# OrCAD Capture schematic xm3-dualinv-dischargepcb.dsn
size A; title: XM3 Discharge PCB; rev: V1; company: Wolfspeed; note: 535 W Research Center Blvd.; note: Fayetteville, AR, 72701
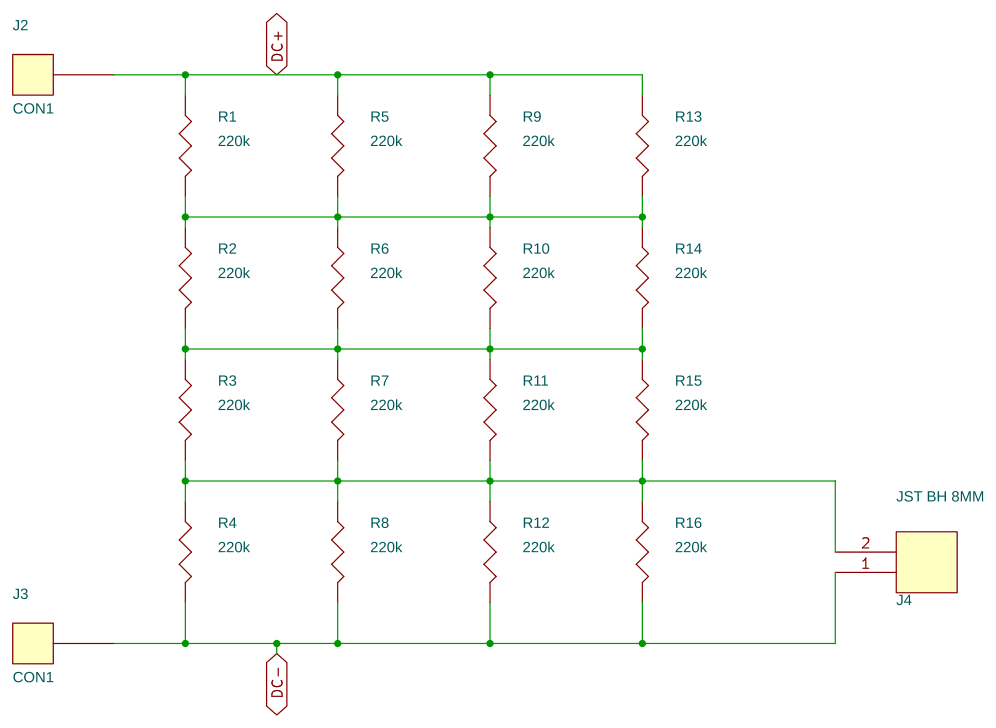
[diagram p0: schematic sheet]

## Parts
J2  CON1  [CON_1x1]
J3  CON1  [CON_1x1]
J4  JST BH 8MM  [CON_JST-BHS-8MM-2PIN]
R1  220k  [RESC6432X70N]
R2  220k  [RESC6432X70N]
R3  220k  [RESC6432X70N]
R4  220k  [RESC6432X70N]
R5  220k  [RESC6432X70N]
R6  220k  [RESC6432X70N]
R7  220k  [RESC6432X70N]
R8  220k  [RESC6432X70N]
R9  220k  [RESC6432X70N]
R10  220k  [RESC6432X70N]
R11  220k  [RESC6432X70N]
R12  220k  [RESC6432X70N]
R13  220k  [RESC6432X70N]
R14  220k  [RESC6432X70N]
R15  220k  [RESC6432X70N]
R16  220k  [RESC6432X70N]

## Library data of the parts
J2 J3 = CON1
J4 = CON2: CONN HEADER SMD R/A 2POS 8MM; CLASS: IO; Company Part Status: New; Contact Voltage: 600V; Manufacturer: JST Sales America Inc.; Manufacturer PN: SM02(8.0)B-BHS-1-TB(LF)(SN); PART_NUMBER: TMP-1676; STEP_MODEL: SM02_8_B-BHS-1-TB.STEP
R1-R16 = R: RES SMD 220K OHM 1% 2W 2512; CLASS: DISCRETE; Company Part Status: New; Manufacturer: TE Connectivity AMP Connectors; Manufacturer PN: 2176071-6; PART_NUMBER: TMP-659; Package Size: 2512 (6432 Metric); Rated Power: 2W; Temperature Coefficient: 100ppm/C; Tolerance: 1%

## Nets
DC+: J2.1 R1.1 R5.1 R9.1 R13.1
DC-: J3.1 J4.1 R4.2 R8.2 R12.2 R16.2
N234316: R1.2 R2.1 R5.2 R6.1 R9.2 R10.1 R13.2 R14.1
N234320: R2.2 R3.1 R6.2 R7.1 R10.2 R11.1 R14.2 R15.1
N234326: J4.2 R3.2 R4.1 R7.2 R8.1 R11.2 R12.1 R15.2 R16.1
